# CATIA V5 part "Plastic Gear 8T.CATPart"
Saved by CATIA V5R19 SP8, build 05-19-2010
Part number: Plastic Gear 8T
Definition: Plastic Gear 8T
Nomenclature: 83450
Source: Unknown
Bounding box of the stored display mesh (mm): x -5.05 to 5.05, y -5.05 to 5.05, z -1.5 to 10.5
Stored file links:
  D:\Documents\1_Travail\1 - ac-limoges.fr\ac-limoges.fr\Emmanuel Maynard - STI2D_Turgot\1 - IT-I2D\Activités_IT_Première\IT_3_Abris_bus\Maquettes numériques\Abribus_eleve\Plastic Gear 8T.CATPart
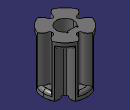
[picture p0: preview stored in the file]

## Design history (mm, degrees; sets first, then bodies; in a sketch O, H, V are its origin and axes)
AxisSystem1: origin (0, 0, 0), X (1, 0, 0), Y (0, 1, 0), Z (0, 0, 1)
Body1 "Corps de pièce" (main body)
  Solid1 "Ô²½Ç2": solid without history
